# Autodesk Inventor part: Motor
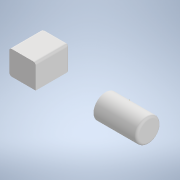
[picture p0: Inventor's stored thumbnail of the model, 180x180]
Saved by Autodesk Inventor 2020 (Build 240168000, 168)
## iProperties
Created: 2019-07
Part Number: Motor
Material: Generic
Document SubType Name: Modeling
Designer: cl
Density: 1 g/cm^3
Appearance: Default
Author: cl
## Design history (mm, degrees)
sketch "Sketch1"
  geometry: L1 (-90, -33.345)-(-90, -203.345) reference; L2 (-90, -203.345)-(60, -203.345) reference; L3 (60, -203.345)-(60, -33.345) reference; L4 (-90, -33.345)-(60, -33.345) reference; L5 (-350.058, -51.421)-(-349.351, -207.934) reference; L6 (-370.14, -33.345)-(-260.591, -33.345); L7 (-260.591, -33.345)-(-260.591, 66.655); L8 (-260.591, 66.655)-(-370.591, 66.655); L9 (-370.591, 66.655)-(-370.14, -33.345); 3 further points
  constraints: 16 end point, 3 horizontal, 2 vertical, 1 collinear, 1 parallel, 1 perpendicular, 5 other
  dimensions: "d0" = 20 distance between parallel lines of L5 L9; "d2" = 100 distance between parallel lines of L4 L8; "d13" = 110 distance of L7.end L8.end
extrude "Extrusion1" new body sketch "Sketch1" distance "d3" = 140; taper "d4" = 0 deg
workplane "Work Plane1"
sketch "Sketch2"
  geometry: L1 (10, -10)-(-90, -10) reference; L2 (10, -10)-(10, 90) reference; L3 (10, 90)-(-130, 90) reference; C1 r 50 at (-90, 40)
  constraints: 2 tangent, 1 centre point
  dimensions: "d11" = 100 distance from line of L2 C1.centre
extrude "Extrusion2" join sketch "Sketch2" distance "d8" = 180; taper "d9" = 0 deg
fillet "Fillet3" dims "d12" = 10
body "Solid1"
node "Reference1"
